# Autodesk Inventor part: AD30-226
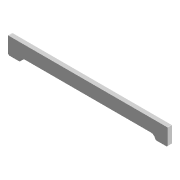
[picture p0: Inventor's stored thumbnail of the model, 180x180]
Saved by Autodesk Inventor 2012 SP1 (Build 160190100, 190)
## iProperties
Shininess: 0.0
Length Units: 11269
Angle Units: 11279
Time Units: 11290
Mass Units: 11283
Length Display Precision: 3
Angle Display Precision: 2
Compacted: True
Created: 2000-06
Part Number: AD30-226
Project: BONDING PRESS
Description: RISER RAIL
Document SubType Name: Modeling
Designer: Ron
Material: Aluminum-6061
Density: 1 g/cm^3
Density: 0.0
Volumn: 0.0
Area: 0.0
PropertySet Name: Model Information
Control State: 0
Master: False
Checked Out: False
Title: RISER RAIL
Author: Ron
Revision Number: A
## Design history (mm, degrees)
node "Extrusion1" dims "d5" = 12.7, "d6" = 0
  sketch "Sketch1"
    geometry: L1 (240, 0)-(-240, 0); L2 (-240, 0)-(-240, 50.8); L3 (-240, 50.8)-(240, 50.8); L4 (240, 50.8)-(240, 0); L5 (201.9, 50.8)-(-201.9, 50.8); L6 (-201.9, 50.8)-(-201.9, 38.1); L7 (-201.9, 38.1)-(201.9, 38.1); L8 (201.9, 38.1)-(201.9, 50.8); 2 further points
    constraints: 16 end point, 4 parallel, 2 horizontal, 2 perpendicular, 1 coincident, 1 midpoint, 1 point on line
    dimensions: "d0" = 480 distance of L2.end L3.end; "d1" = 50.8 distance of L1.end L2.end; "d2" = 38.1 distance between parallel lines of L4 L8; "d3" = 38.1 distance between parallel lines of L2 L6 (= d2); "d4" = 12.7 distance between parallel lines of L3 L7
node "Chamfer1" dims "d7" = 3.175, "d8" = 3.175, "d20" = 45 deg
node "Fillet1" dims "d9" = 12.7
body "Solid1"
